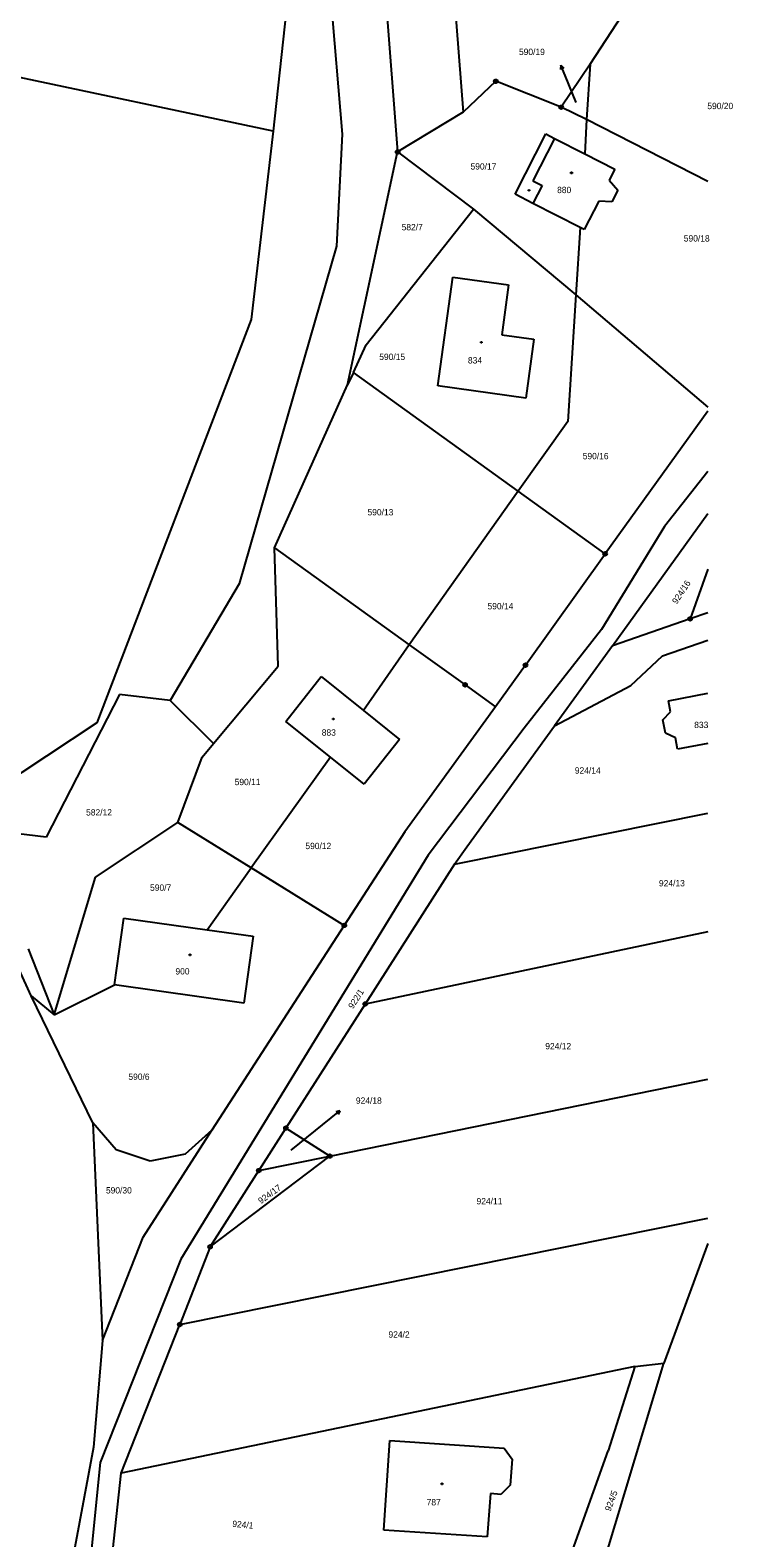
# Model space of a CAD drawing. Extents: x -770973 to -770265, y -1049936 to -1049427.
# Drawn here: x -770521.2 to -770426.7, y -1049731.9 to -1049529.2 of the extents above; entities that cross this region are included whole.
import ezdxf

# ---------------------------------------------------------------- set-up
doc = ezdxf.new("R2010")
doc.units = 0
for name, color, linetype in [('Vrstva 1', 7, 'Continuous'), ('Vrstva 13', 7, 'Continuous'), ('Vrstva 14', 7, 'Continuous'), ('Vrstva 15', 7, 'Continuous'), ('Vrstva 16', 7, 'Continuous'), ('Vrstva 2', 7, 'Continuous'), ('Vrstva 25', 7, 'Continuous'), ('Vrstva 28', 7, 'Continuous')]:
    doc.layers.add(name, color=color, linetype=linetype)

msp = doc.modelspace()

# ---------------------------------------------------------------- linework, layer by layer
at = {"layer": 'Vrstva 1'}
for p, q in [((-770484.17, -1049502.96), (-770488.51, -1049542.82)), ((-770465.79, -1049504.34), (-770462.96, -1049540.28)), ((-770474.68, -1049508.11), (-770471.77, -1049545.62)), ((-770481.81, -1049512.66), (-770479.21, -1049543.24)), ((-770445.89, -1049533.82), (-770440.17, -1049525.01)), ((-770445.89, -1049533.82), (-770449.79, -1049539.6)), ((-770445.89, -1049533.82), (-770446.36, -1049541.26)), ((-770488.51, -1049542.82), (-770527.26, -1049534.61)), ((-770458.58, -1049536.12), (-770462.96, -1049540.28)), ((-770449.79, -1049539.6), (-770458.58, -1049536.12)), ((-770446.36, -1049541.26), (-770449.79, -1049539.6)), ((-770462.96, -1049540.28), (-770471.77, -1049545.62)), ((-770446.36, -1049541.26), (-770446.61, -1049545.88)), ((-770430.07, -1049549.6), (-770446.36, -1049541.26)), ((-770488.51, -1049542.82), (-770491.47, -1049568.13)), ((-770479.21, -1049543.24), (-770479.99, -1049558.29)), ((-770455.99, -1049551.31), (-770451.86, -1049543.2)), ((-770451.86, -1049543.2), (-770450.7, -1049543.79)), ((-770450.7, -1049543.79), (-770446.61, -1049545.88)), ((-770478.5, -1049576.94), (-770471.77, -1049545.62)), ((-770471.77, -1049545.62), (-770461.57, -1049553.31)), ((-770446.61, -1049545.88), (-770442.59, -1049547.92)), ((-770442.59, -1049547.92), (-770443.34, -1049549.39)), ((-770443.34, -1049549.39), (-770442.17, -1049550.74)), ((-770453.58, -1049552.54), (-770455.99, -1049551.31)), ((-770444.74, -1049552.21), (-770446.71, -1049556.05)), ((-770442.96, -1049552.34), (-770444.74, -1049552.21)), ((-770442.17, -1049550.74), (-770442.96, -1049552.34)), ((-770476, -1049571.53), (-770461.57, -1049553.31)), ((-770461.57, -1049553.31), (-770447.83, -1049564.82)), ((-770447.23, -1049555.79), (-770453.58, -1049552.54)), ((-770447.23, -1049555.79), (-770447.83, -1049564.82)), ((-770446.71, -1049556.05), (-770447.23, -1049555.79)), ((-770479.99, -1049558.29), (-770493.09, -1049603.65)), ((-770466.37, -1049577.06), (-770464.37, -1049562.46)), ((-770464.37, -1049562.46), (-770456.85, -1049563.5)), ((-770456.85, -1049563.5), (-770457.77, -1049570.2)), ((-770447.83, -1049564.82), (-770448.9, -1049581.83)), ((-770447.83, -1049564.82), (-770430.07, -1049579.93)), ((-770491.47, -1049568.13), (-770512.22, -1049622.34)), ((-770457.77, -1049570.2), (-770453.47, -1049570.79)), ((-770477.7, -1049575.26), (-770476, -1049571.53)), ((-770453.47, -1049570.79), (-770454.54, -1049578.7)), ((-770477.7, -1049575.26), (-770478.5, -1049576.94)), ((-770455.56, -1049591.21), (-770477.7, -1049575.26)), ((-770488.33, -1049598.82), (-770478.5, -1049576.94)), ((-770454.54, -1049578.7), (-770466.37, -1049577.06)), ((-770430.07, -1049580.48), (-770443.87, -1049599.64)), ((-770448.9, -1049581.83), (-770455.56, -1049591.21)), ((-770430.07, -1049588.56), (-770435.89, -1049595.97)), ((-770455.56, -1049591.21), (-770470.2, -1049611.87)), ((-770443.87, -1049599.64), (-770455.56, -1049591.21)), ((-770442.88, -1049611.99), (-770430.07, -1049594.22)), ((-770435.89, -1049595.97), (-770444.36, -1049609.79)), ((-770488.33, -1049598.82), (-770470.2, -1049611.87)), ((-770487.84, -1049614.75), (-770488.33, -1049598.82)), ((-770454.58, -1049614.6), (-770443.87, -1049599.64)), ((-770430.07, -1049601.71), (-770432.46, -1049608.39)), ((-770493.09, -1049603.65), (-770502.34, -1049619.36)), ((-770432.46, -1049608.39), (-770442.88, -1049611.99)), ((-770430.07, -1049607.55), (-770432.46, -1049608.39)), ((-770444.36, -1049609.79), (-770454.76, -1049623.08)), ((-770470.2, -1049611.87), (-770476.37, -1049620.7)), ((-770470.2, -1049611.87), (-770462.7, -1049617.25)), ((-770442.88, -1049611.99), (-770450.7, -1049622.78)), ((-770436.17, -1049613.37), (-770430.07, -1049611.26)), ((-770496.52, -1049625.12), (-770487.84, -1049614.75)), ((-770454.58, -1049614.6), (-770458.6, -1049620.19)), ((-770440.44, -1049617.34), (-770436.17, -1049613.37)), ((-770486.82, -1049622.17), (-770482.06, -1049616.14)), ((-770482.06, -1049616.14), (-770476.37, -1049620.7)), ((-770509.16, -1049618.53), (-770519.02, -1049637.74)), ((-770502.34, -1049619.36), (-770509.16, -1049618.53)), ((-770462.7, -1049617.25), (-770458.6, -1049620.19)), ((-770450.7, -1049622.78), (-770440.44, -1049617.34)), ((-770435.36, -1049619.39), (-770430.07, -1049618.37)), ((-770502.34, -1049619.36), (-770496.52, -1049625.12)), ((-770476.37, -1049620.7), (-770471.53, -1049624.58)), ((-770458.6, -1049620.19), (-770470.8, -1049637.02)), ((-770436.13, -1049621.93), (-770435.08, -1049620.89)), ((-770435.08, -1049620.89), (-770435.36, -1049619.39)), ((-770512.22, -1049622.34), (-770527.14, -1049632.24)), ((-770480.81, -1049626.98), (-770486.82, -1049622.17)), ((-770454.76, -1049623.08), (-770467.68, -1049640.16)), ((-770462.47, -1049639.01), (-770450.7, -1049622.78)), ((-770435.77, -1049623.73), (-770436.13, -1049621.93)), ((-770498.05, -1049626.95), (-770496.52, -1049625.12)), ((-770471.53, -1049624.58), (-770476.29, -1049630.61)), ((-770434.41, -1049624.39), (-770435.77, -1049623.73)), ((-770434.14, -1049625.91), (-770434.41, -1049624.39)), ((-770430.07, -1049625.13), (-770434.14, -1049625.91)), ((-770501.33, -1049635.76), (-770498.05, -1049626.95)), ((-770480.81, -1049626.98), (-770491.45, -1049641.85)), ((-770476.29, -1049630.61), (-770480.81, -1049626.98)), ((-770464.14, -1049641.36), (-770430.07, -1049634.5)), ((-770519.02, -1049637.74), (-770524.21, -1049637.09)), ((-770512.38, -1049643.09), (-770501.33, -1049635.76)), ((-770491.45, -1049641.85), (-770501.33, -1049635.76)), ((-770470.8, -1049637.02), (-770478.94, -1049649.59)), ((-770464.14, -1049641.36), (-770462.47, -1049639.01)), ((-770467.68, -1049640.16), (-770500.91, -1049694.44)), ((-770464.14, -1049641.36), (-770476.12, -1049660.15)), ((-770517.95, -1049661.6), (-770512.38, -1049643.09)), ((-770497.36, -1049650.19), (-770491.45, -1049641.85)), ((-770478.94, -1049649.59), (-770491.45, -1049641.85)), ((-770521.04, -1049659.06), (-770525.45, -1049649.4)), ((-770509.84, -1049657.57), (-770508.57, -1049648.62)), ((-770508.57, -1049648.62), (-770497.36, -1049650.19)), ((-770497.36, -1049650.19), (-770491.17, -1049651.05)), ((-770478.94, -1049649.59), (-770496.75, -1049677.11)), ((-770491.17, -1049651.05), (-770492.46, -1049660.02)), ((-770430.07, -1049650.45), (-770476.12, -1049660.15)), ((-770521.43, -1049652.75), (-770517.95, -1049661.6)), ((-770517.95, -1049661.6), (-770509.84, -1049657.57)), ((-770492.46, -1049660.02), (-770509.84, -1049657.57)), ((-770521.04, -1049659.06), (-770517.95, -1049661.6)), ((-770512.75, -1049676.12), (-770521.04, -1049659.06)), ((-770476.12, -1049660.15), (-770486.79, -1049676.83)), ((-770480.89, -1049680.6), (-770430.07, -1049670.27)), ((-770512.75, -1049676.12), (-770511.43, -1049705.36)), ((-770509.59, -1049679.74), (-770512.75, -1049676.12)), ((-770505.99, -1049691.51), (-770496.75, -1049677.11)), ((-770496.75, -1049677.11), (-770500.33, -1049680.32)), ((-770486.79, -1049676.83), (-770490.44, -1049682.54)), ((-770480.89, -1049680.6), (-770486.79, -1049676.83)), ((-770505.04, -1049681.29), (-770509.59, -1049679.74)), ((-770500.33, -1049680.32), (-770505.04, -1049681.29)), ((-770496.98, -1049692.78), (-770480.89, -1049680.6)), ((-770490.44, -1049682.54), (-770480.89, -1049680.6)), ((-770496.98, -1049692.78), (-770490.44, -1049682.54)), ((-770501.06, -1049703.23), (-770430.07, -1049688.93)), ((-770511.43, -1049705.36), (-770505.99, -1049691.51)), ((-770496.98, -1049692.78), (-770501.06, -1049703.23)), ((-770430.07, -1049692.34), (-770436, -1049708.43)), ((-770500.91, -1049694.44), (-770511.76, -1049721.8)), ((-770508.95, -1049723.22), (-770501.06, -1049703.23)), ((-770511.43, -1049705.36), (-770512.65, -1049719.7)), ((-770439.89, -1049708.86), (-770508.95, -1049723.22)), ((-770443.79, -1049734.32), (-770436, -1049708.43)), ((-770439.89, -1049708.86), (-770443.45, -1049720.22)), ((-770439.89, -1049708.86), (-770436, -1049708.43)), ((-770512.65, -1049719.7), (-770523.05, -1049775.51)), ((-770473.61, -1049730.89), (-770472.84, -1049718.84)), ((-770472.84, -1049718.84), (-770457.43, -1049719.86)), ((-770457.43, -1049719.86), (-770456.38, -1049721.32)), ((-770449.16, -1049736.12), (-770443.45, -1049720.22)), ((-770511.76, -1049721.8), (-770514.86, -1049752.7)), ((-770456.38, -1049721.32), (-770456.63, -1049724.81)), ((-770510.82, -1049740.97), (-770508.95, -1049723.22)), ((-770459.3, -1049725.96), (-770459.72, -1049731.77)), ((-770457.89, -1049726.09), (-770459.3, -1049725.96)), ((-770456.63, -1049724.81), (-770457.89, -1049726.09)), ((-770459.72, -1049731.77), (-770473.61, -1049730.89))]:
    msp.add_line(p, q, dxfattribs=at)
at = {"layer": 'Vrstva 13'}
for p, q in [((-770447.79, -1049538.96), (-770449.27, -1049535.36)), ((-770486.08, -1049679.8), (-770480.71, -1049675.45))]:
    msp.add_line(p, q, dxfattribs=at)
at = {"layer": 'Vrstva 16'}
for p, q in [((-770449.84, -1049533.97), (-770449.88, -1049534.53)), ((-770449.27, -1049535.36), (-770449.84, -1049533.97)), ((-770449.84, -1049533.97), (-770449.42, -1049534.34)), ((-770480.71, -1049675.45), (-770479.54, -1049674.51)), ((-770479.54, -1049674.51), (-770480.09, -1049674.63)), ((-770479.54, -1049674.51), (-770479.78, -1049675.01))]:
    msp.add_line(p, q, dxfattribs=at)
at = {"layer": 'Vrstva 2'}
for p, q in [((-770450.7, -1049543.79), (-770453.6, -1049549.5)), ((-770453.6, -1049549.5), (-770452.35, -1049550.13)), ((-770452.35, -1049550.13), (-770453.58, -1049552.54))]:
    msp.add_line(p, q, dxfattribs=at)
at = {"layer": 'Vrstva 25'}
for p, q in [((-770448.47, -1049548.35), (-770448.32, -1049548.35)), ((-770448.47, -1049548.5), (-770448.47, -1049548.35)), ((-770448.32, -1049548.5), (-770448.47, -1049548.5)), ((-770448.32, -1049548.35), (-770448.32, -1049548.5)), ((-770454.19, -1049550.69), (-770454.04, -1049550.69)), ((-770454.19, -1049550.84), (-770454.19, -1049550.69)), ((-770454.04, -1049550.84), (-770454.19, -1049550.84)), ((-770454.04, -1049550.69), (-770454.04, -1049550.84)), ((-770460.58, -1049571.13), (-770460.43, -1049571.13)), ((-770460.58, -1049571.28), (-770460.58, -1049571.13)), ((-770460.43, -1049571.28), (-770460.58, -1049571.28)), ((-770460.43, -1049571.13), (-770460.43, -1049571.28)), ((-770480.48, -1049621.76), (-770480.33, -1049621.76)), ((-770480.48, -1049621.91), (-770480.48, -1049621.76)), ((-770480.33, -1049621.91), (-770480.48, -1049621.91)), ((-770480.33, -1049621.76), (-770480.33, -1049621.91)), ((-770499.75, -1049653.46), (-770499.6, -1049653.46)), ((-770499.75, -1049653.61), (-770499.75, -1049653.46)), ((-770499.6, -1049653.61), (-770499.75, -1049653.61)), ((-770499.6, -1049653.46), (-770499.6, -1049653.61)), ((-770465.87, -1049724.58), (-770465.72, -1049724.58)), ((-770465.87, -1049724.73), (-770465.87, -1049724.58)), ((-770465.72, -1049724.73), (-770465.87, -1049724.73)), ((-770465.72, -1049724.58), (-770465.72, -1049724.73))]:
    msp.add_line(p, q, dxfattribs=at)
at = {"layer": 'Vrstva 28'}
for centre, radius in [((-770458.58, -1049536.12), 0.25), ((-770458.58, -1049536.12), 0.005), ((-770449.79, -1049539.6), 0.25), ((-770449.79, -1049539.6), 0.005), ((-770471.77, -1049545.62), 0.25), ((-770471.77, -1049545.62), 0.005), ((-770443.87, -1049599.64), 0.25), ((-770443.87, -1049599.64), 0.005), ((-770432.46, -1049608.39), 0.25), ((-770432.46, -1049608.39), 0.005), ((-770454.58, -1049614.6), 0.25), ((-770454.58, -1049614.6), 0.005), ((-770462.7, -1049617.25), 0.25), ((-770462.7, -1049617.25), 0.005), ((-770478.94, -1049649.59), 0.25), ((-770478.94, -1049649.59), 0.005), ((-770476.12, -1049660.15), 0.25), ((-770476.12, -1049660.15), 0.005), ((-770486.79, -1049676.83), 0.25), ((-770486.79, -1049676.83), 0.005), ((-770480.89, -1049680.6), 0.25), ((-770480.89, -1049680.6), 0.005), ((-770490.44, -1049682.54), 0.25), ((-770490.44, -1049682.54), 0.005), ((-770496.98, -1049692.78), 0.25), ((-770496.98, -1049692.78), 0.005), ((-770501.06, -1049703.23), 0.25), ((-770501.06, -1049703.23), 0.005)]:
    msp.add_circle(centre, radius, dxfattribs=at)

# ---------------------------------------------------------------- texts
at = {"layer": 'Vrstva 14'}
for s, height, p in [('590/19', 0.05, (-770447.91, -1049538.96)), ('590/20', 0.85, (-770430.14, -1049539.86)), ('590/17', 0.85, (-770461.97, -1049547.98)), ('582/7', 0.85, (-770471.23, -1049556.15)), ('590/18', 0.85, (-770433.3, -1049557.66)), ('590/15', 0.85, (-770474.24, -1049573.58)), ('590/16', 0.85, (-770446.89, -1049586.92)), ('590/13', 0.85, (-770475.82, -1049594.47)), ('590/14', 0.85, (-770459.69, -1049607.1)), ('924/14', 0.85, (-770447.95, -1049629.18)), ('590/11', 0.85, (-770493.68, -1049630.73)), ('582/12', 0.85, (-770513.65, -1049634.81)), ('590/12', 0.85, (-770484.17, -1049639.33)), ('924/13', 0.85, (-770436.64, -1049644.34)), ('590/7', 0.85, (-770505.05, -1049644.93)), ('924/12', 0.85, (-770451.92, -1049666.24)), ('590/6', 0.85, (-770507.96, -1049670.35)), ('924/18', 0.05, (-770486.2, -1049679.8)), ('590/30', 0.85, (-770510.98, -1049685.62)), ('924/11', 0.85, (-770461.16, -1049687.08)), ('924/2', 0.85, (-770473, -1049705))]:
    msp.add_text(s, height=height, dxfattribs=at).set_placement(p)
for s, rotation, p in [('924/16', 56.8412, (-770434.23, -1049606.46)), ('922/1', 57.4219, (-770477.77, -1049660.88)), ('924/17', 35.8552, (-770490.15, -1049687.07)), ('924/5', 69.8837, (-770443.15, -1049728.41)), ('924/1', 354.5471, (-770494.03, -1049730.42))]:
    msp.add_text(s, height=0.85, rotation=rotation, dxfattribs=at).set_placement(p)
at = {"layer": 'Vrstva 15'}
for s, p in [('880', (-770450.33, -1049551.15)), ('834', (-770462.32, -1049574.05)), ('883', (-770481.97, -1049624.08)), ('833', (-770431.9, -1049623.06)), ('900', (-770501.64, -1049656.18)), ('787', (-770467.87, -1049727.55))]:
    msp.add_text(s, height=0.85, dxfattribs=at).set_placement(p)
at = {"layer": 'Vrstva 16'}
for s, p in [('590/19', (-770455.46, -1049532.59)), ('924/18', (-770477.38, -1049673.56))]:
    msp.add_text(s, height=0.85, dxfattribs=at).set_placement(p)

doc.saveas('drawing.dxf')
